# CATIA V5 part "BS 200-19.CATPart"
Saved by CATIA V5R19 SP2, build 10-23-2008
Part number: BS 200-19
Bounding box of the stored display mesh (mm): x -12.497 to 12.497, y -12.358 to 12.358, z 0 to 68
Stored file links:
  C:\Users\Bora\Desktop\3D Katı model\BS serisi\BS 200\BS 200-19.CATPart
  C:\Program Files\Dassault Systemes\B19\intel_a\reffiles\standard\MetricThickPitch.txt
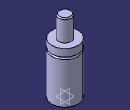
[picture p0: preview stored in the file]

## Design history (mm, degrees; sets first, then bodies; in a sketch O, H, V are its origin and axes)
Body1 (main body)
  Sketch1 on yz-plane, origin (0, 0, 0), H (0, 1, 0), V (0, 0, 1)
    point P1 (6, 67)
    point P3 (6, 67)
    point P5 (12.5, 41)
    point P6 (12.5, 39)
    point P8 (12.5, 39)
    point P9 (12.5, 41)
    line L1 (6, 67) -> (6, 48)
    arc A1 centre (5, 67) radius 1 from (6, 67) to (5, 68) ccw
    arc A2 centre (12.5, 40) radius 1 from (12.5, 41) to (12.5, 39) ccw
    line L2 (12.5, 0) -> (12.5, 39)
    line L3 (12.5, 41) -> (12.5, 48)
    line L4 (5, 68) -> (0, 68)
    point P11 (0, 68)
    line L5 (6, 48) -> (12.5, 48)
    line L6 (12.5, 0) -> (0, 0)
    coincidence: P11 V, P1 P3, P5 P9, P6 P8
    tangency: L4 A1
    horizontal: L5 H, L6 H
  Shaft1: profile Sketch1, axis Sketch1.V, angle 360
  Sketch2 on face of Shaft1 from Sketch1.L6, origin (0, 0, 0), H (1, 0, 0), V (0, -1, 0)
    point P1 (0, 0)
  Hole1: placed by Sketch2, at (0, 0, 0) direction (0, 0, 1), diameter 4.917, depth 4, threaded "M6", thread diameter 6, thread depth 4, pitch 1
